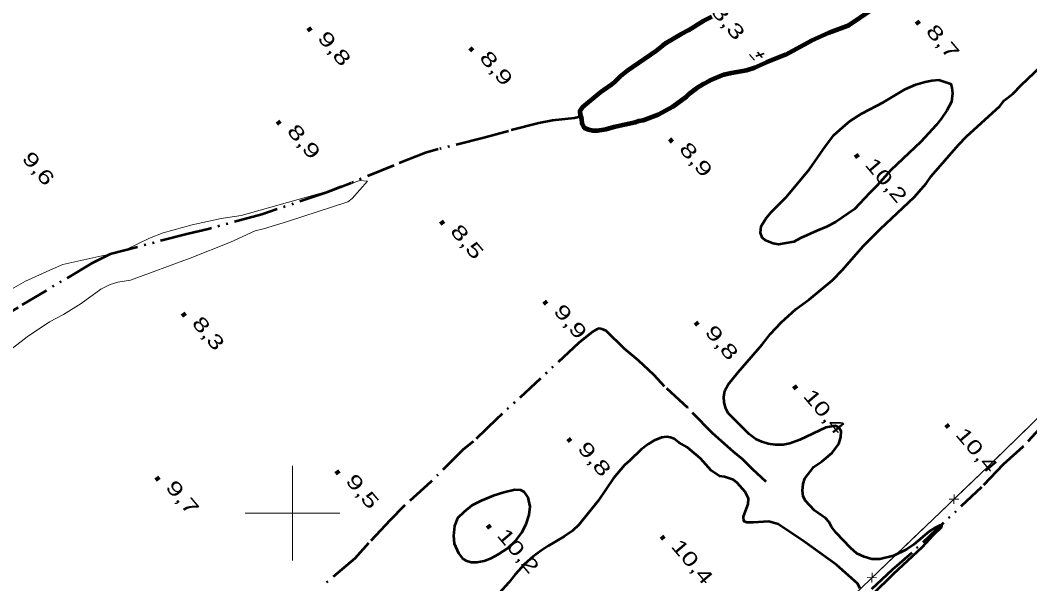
# Model space of a CAD drawing. Extents: x 386081 to 389416, y 5130568 to 5134082.
# Drawn here: x 386742.5 to 386955.8, y 5132585.1 to 5132704.2 of the extents above; entities that cross this region are included whole.
import ezdxf
from ezdxf.enums import TextEntityAlignment as Align

# ---------------------------------------------------------------- set-up
doc = ezdxf.new("R2010")
doc.units = 0
doc.header["$LTSCALE"] = 1.2
doc.linetypes.add('DASH_DOUBLE_DOT', pattern=[9.2, 5, -1.2, 0.3, -1.2, 0.3, -1.2])
for name, color, linetype, lineweight in [('1', 7, 'Continuous', 53), ('2', 7, 'Continuous', 13), ('3', 7, 'Continuous', 140), ('37', 7, 'Continuous', 13), ('4', 7, 'DASH_DOUBLE_DOT', 53), ('61', 7, 'Continuous', 13)]:
    doc.layers.add(name, color=color, linetype=linetype, lineweight=lineweight)

msp = doc.modelspace()

# ---------------------------------------------------------------- linework, layer by layer
at = {"layer": '1'}
for points in [[(386922.59, 5132582.88), (386926.95, 5132587.19), (386933.05, 5132592.85), (386935.42, 5132595.43), (386937.11, 5132597.09), (386937.17, 5132597.4), (386936.8, 5132597.4), (386935.62, 5132596.85), (386934.5, 5132596.11), (386931.26, 5132593.41), (386929.7, 5132592.36), (386926.97, 5132591.02), (386924.11, 5132590.29), (386922.38, 5132590.29), (386920.77, 5132590.79), (386919.22, 5132591.48), (386917.92, 5132592.66), (386914.84, 5132595.88), (386913.86, 5132597.12), (386913.36, 5132598.11), (386912.63, 5132598.98), (386910.28, 5132600.6), (386908.3, 5132602.7), (386907.88, 5132603.63), (386907.76, 5132604.75), (386907.89, 5132606.23), (386908.27, 5132607.34), (386910.14, 5132609.8), (386911.82, 5132610.97), (386914, 5132612.75), (386915.43, 5132614.66), (386915.87, 5132616.08), (386915.94, 5132617.38), (386915.45, 5132618.12), (386914.71, 5132618.5), (386912.72, 5132618.13), (386907.19, 5132615.5), (386905.08, 5132614.76), (386903.65, 5132614.46), (386902.04, 5132614.47), (386900.49, 5132614.66), (386899.19, 5132615.1), (386897.9, 5132615.66), (386896.48, 5132616.71), (386892.04, 5132621.18), (386891.55, 5132622.17), (386891.18, 5132623.4), (386891.12, 5132624.58), (386891.38, 5132625.94), (386892.07, 5132627.23), (386894.19, 5132629.82), (386899.24, 5132635.67), (386901.02, 5132637.95), (386903.23, 5132640.33), (386906.38, 5132643.16), (386909.16, 5132645.22), (386914.11, 5132649.28), (386916.17, 5132651.4), (386920.67, 5132656.51), (386924.26, 5132660.13), (386931.33, 5132666.82), (386933.86, 5132669.69), (386934.92, 5132671.24), (386940.68, 5132677.86), (386942.37, 5132679.65), (386949.47, 5132686.05), (386950.37, 5132687.23), (386952.26, 5132688.71), (386953.96, 5132690.51), (386958.2, 5132694.51)], [(386919.93, 5132584.06), (386919.37, 5132585.12), (386914.93, 5132589.09), (386907.89, 5132594.18), (386902.64, 5132597.72), (386900.66, 5132598.22), (386897.37, 5132598.05), (386896.01, 5132598.06), (386895.39, 5132598.31), (386895.27, 5132599.3), (386896.28, 5132601.89), (386896.32, 5132603.13), (386895.61, 5132604.5), (386893.93, 5132606.41), (386893.2, 5132607.04), (386891.29, 5132607.73), (386890.22, 5132607.86), (386888.43, 5132609.05), (386886.23, 5132611.55), (386883.95, 5132613.45), (386883.42, 5132614), (386881.66, 5132614.98), (386880.67, 5132615.72), (386879.87, 5132616.03), (386879.12, 5132616.16), (386877.94, 5132615.98), (386876.45, 5132615.37), (386875.15, 5132614.57), (386873.66, 5132613.46), (386871.29, 5132611.12), (386870.17, 5132610.14), (386867.8, 5132607.43), (386864.56, 5132602.63), (386860.51, 5132597.52), (386859.14, 5132596.29), (386857.4, 5132595.06), (386853.98, 5132593.04), (386852.49, 5132592.05), (386850.88, 5132590.83), (386849.01, 5132589.23), (386847.08, 5132587.07), (386845.71, 5132585.35), (386843.66, 5132583.08)]]:
    msp.add_lwpolyline(points, dxfattribs=at)
for points in [[(386932.75, 5132678.5), (386926.45, 5132672.53), (386923.46, 5132669.2), (386921.9, 5132667.66), (386918.72, 5132664.27), (386914.74, 5132661.57), (386912.81, 5132660.52), (386910.76, 5132659.73), (386907.35, 5132658.19), (386905.92, 5132657.39), (386902.69, 5132656.79), (386901.57, 5132657.04), (386899.97, 5132657.66), (386899.23, 5132658.28), (386898.86, 5132659.27), (386899.05, 5132660.69), (386900.11, 5132662.36), (386901.17, 5132663.65), (386904.29, 5132666.86), (386909.22, 5132672.71), (386912.59, 5132677.64), (386914.4, 5132679.92), (386916.33, 5132681.71), (386917.76, 5132682.88), (386920.31, 5132684.54), (386924.85, 5132686.94), (386929.46, 5132689.64), (386931.69, 5132690.62), (386933.68, 5132691.24), (386935.05, 5132691.48), (386936.54, 5132691.6), (386939.08, 5132690.79), (386939.32, 5132689.92), (386939.44, 5132688.81), (386939.24, 5132687.01), (386938.24, 5132685.16), (386937.05, 5132683.37), (386935.99, 5132682.08)], [(386846.98, 5132604.92), (386844.69, 5132604.37), (386842.39, 5132603.7), (386839.91, 5132602.6), (386837.93, 5132601.62), (386836.25, 5132600.33), (386834.88, 5132598.98), (386834.25, 5132597.37), (386834.06, 5132595.21), (386834.17, 5132593.61), (386835.09, 5132591.57), (386835.95, 5132590.45), (386836.63, 5132590.02), (386837.74, 5132589.64), (386838.98, 5132589.64), (386840.53, 5132589.94), (386841.96, 5132590.49), (386843.57, 5132591.35), (386845.5, 5132592.64), (386847.3, 5132594.3), (386848.49, 5132595.96), (386849.36, 5132597.69), (386849.99, 5132599.66), (386850.25, 5132601.39), (386849.82, 5132603.3), (386849.02, 5132604.48), (386848.28, 5132604.85)]]:
    msp.add_lwpolyline(points, close=True, dxfattribs=at)
at = {"layer": '2'}
msp.add_lwpolyline([(386736.7, 5132631.73), (386743.99, 5132637.32), (386748.7, 5132640.47), (386751.64, 5132642.01), (386755.35, 5132644.37), (386759.52, 5132647.37), (386761.47, 5132648.37), (386763.11, 5132648.84), (386765.77, 5132649.3), (386778.38, 5132653.91), (386786.95, 5132657.32), (386792.15, 5132659.74), (386793.91, 5132660.15), (386798.98, 5132661.66), (386811.74, 5132665.83), (386812.64, 5132666.55), (386815.88, 5132670.24), (386814.21, 5132670.33), (386812.38, 5132669.73), (386809.96, 5132669.16), (386806.97, 5132667.98), (386789.17, 5132662.94), (386784.95, 5132662.28), (386778.81, 5132660.95), (386772.68, 5132659.28), (386769.84, 5132658.13), (386765.14, 5132655.9), (386762.15, 5132654.83), (386759.76, 5132654.4), (386751.51, 5132652.57), (386749.36, 5132651.7), (386743.6, 5132649.04), (386740.68, 5132647.34)], dxfattribs=at)
at = {"layer": '3'}
for p, q in [((386931.82, 5132704.03), (386932.33, 5132703.42)), ((386803.3, 5132702.6), (386803.81, 5132701.99)), ((386837.51, 5132698.43), (386838.02, 5132697.82)), ((386796.86, 5132682.92), (386797.37, 5132682.31)), ((386879.69, 5132679.13), (386880.2, 5132678.52)), ((386918.95, 5132675.85), (386919.46, 5132675.24)), ((386831.35, 5132661.75), (386831.86, 5132661.14)), ((386853.16, 5132644.87), (386853.67, 5132644.26)), ((386776.77, 5132642.29), (386777.28, 5132641.68)), ((386885.13, 5132640.43), (386885.64, 5132639.82)), ((386905.9, 5132626.93), (386906.41, 5132626.32)), ((386938.09, 5132618.78), (386938.6, 5132618.17)), ((386858.24, 5132615.82), (386858.75, 5132615.21)), ((386771.2, 5132607.63), (386771.71, 5132607.02)), ((386809.24, 5132608.97), (386809.75, 5132608.36)), ((386841.21, 5132597.48), (386841.72, 5132596.87)), ((386877.98, 5132595.18), (386878.49, 5132594.57))]:
    msp.add_line(p, q, dxfattribs=at)
at = {"layer": '3', "lineweight": 35}
for p, q in [((386896.59, 5132697.01), (386897.63, 5132695.79)), ((386899.69, 5132697.22), (386897.87, 5132696.65)), ((386898.26, 5132697.51), (386899.27, 5132696.32))]:
    msp.add_line(p, q, dxfattribs=at)
at = {"layer": '37'}
for p, q in [((386948.42, 5132611.28), (386955.56, 5132618.28)), ((386940.76, 5132602.94), (386938.76, 5132602.99)), ((386939.74, 5132601.96), (386939.78, 5132603.97)), ((386931.09, 5132594.67), (386938.32, 5132601.58)), ((386923.87, 5132587.76), (386931.09, 5132594.67)), ((386923.42, 5132586.35), (386921.42, 5132586.4)), ((386922.4, 5132585.37), (386922.44, 5132587.37))]:
    msp.add_line(p, q, dxfattribs=at)
for points in [[(386878.76, 5132545.22), (386893.86, 5132559.29), (386912.04, 5132576.44), (386947.01, 5132609.9), (386966.08, 5132628.58), (386986.5, 5132647.98), (387002.12, 5132661.95), (387004.89, 5132659.44), (387006.04, 5132660.44), (387041.04, 5132693.88), (387075.38, 5132725.65), (387084.05, 5132734.26)], [(386941.21, 5132604.35), (386947.01, 5132609.9), (386948.42, 5132611.28)]]:
    msp.add_lwpolyline(points, dxfattribs=at)
at = {"layer": '4', "linetype": 'Continuous', "lineweight": 90}
msp.add_lwpolyline([(386888.57, 5132704.93), (386886.77, 5132704.01), (386883.78, 5132702.16), (386882.16, 5132701.3), (386879.05, 5132699.45), (386878.24, 5132698.9), (386876.74, 5132697.67), (386870.7, 5132693.54), (386869.33, 5132692.43), (386868.09, 5132691.2), (386867.34, 5132690.58), (386865.04, 5132688.92), (386861.3, 5132685.84), (386860.74, 5132685.03), (386860.79, 5132684.23), (386861.04, 5132683.36), (386861.16, 5132682.37), (386861.65, 5132681.5), (386862.52, 5132681.13), (386863.45, 5132680.94), (386864.44, 5132680.94), (386866.18, 5132681.18), (386867.92, 5132681.67), (386872.39, 5132682.65), (386873.2, 5132682.95), (386874.07, 5132683.07), (386877.3, 5132684.3), (386880.35, 5132685.96), (386883.27, 5132688.12), (386883.9, 5132688.73), (386885.39, 5132689.84), (386886.82, 5132690.77), (386888.19, 5132691.51), (386891.18, 5132692.73), (386892.79, 5132693.1), (386895.96, 5132693.65), (386897.7, 5132694.26), (386900.19, 5132695.37), (386904.24, 5132697.02), (386909.65, 5132699.92), (386913.39, 5132701.64), (386917.55, 5132703.17), (386922.35, 5132706.44)], dxfattribs=at)
at = {"layer": '4'}
for points in [[(386860.9, 5132683.86), (386859.61, 5132683.55), (386854.96, 5132683.01), (386852.04, 5132682.46), (386845.64, 5132680.81), (386840.43, 5132679.35), (386830.8, 5132676.97), (386828.14, 5132676.17), (386821.41, 5132673.54), (386812.4, 5132669.8), (386807.25, 5132667.78), (386793.53, 5132663.19), (386782.18, 5132660.07), (386777.96, 5132659.1), (386761.52, 5132654.76), (386757.55, 5132652.8), (386742.09, 5132643.52), (386734.61, 5132639.17), (386731.51, 5132637.57), (386730.21, 5132637.02)], [(386900.11, 5132606.63), (386897.21, 5132609.3), (386895.11, 5132611.41), (386893.2, 5132612.96), (386888.76, 5132616.93), (386883.51, 5132622.27), (386878.63, 5132626.8), (386876.41, 5132629.16), (386873.13, 5132632.26), (386870.17, 5132634.75), (386866.28, 5132638.53), (386865.42, 5132638.91), (386864.8, 5132639.03), (386864.24, 5132638.85), (386863.37, 5132638.36), (386860.51, 5132636.02), (386843.13, 5132619.89), (386838.21, 5132615.15), (386836.03, 5132613.37), (386829.24, 5132606.66), (386823.58, 5132601.55), (386820.65, 5132598.54), (386816.11, 5132593.68), (386813.18, 5132590.41), (386806.51, 5132584.75)], [(386959.43, 5132619.62), (386954.32, 5132614.02), (386950.14, 5132610.27), (386945.59, 5132605.52), (386930.82, 5132591.62), (386926.71, 5132588.05), (386918.68, 5132580.48)]]:
    msp.add_lwpolyline(points, dxfattribs=at)
at = {"layer": '61'}
for p, q in [((386800, 5132590), (386800, 5132610)), ((386790, 5132600), (386810, 5132600))]:
    msp.add_line(p, q, dxfattribs=at)

# ---------------------------------------------------------------- texts
at = {"layer": '3', "width": 1.5}
msp.add_text('    8,3', height=3, rotation=310.294, dxfattribs=at).set_placement((386888.735, 5132705.465), align=Align.CENTER)
at = {"layer": '3'}
for s, width, p in [('8,7    ', 1.45, (386933.65, 5132701.81)), ('9,8    ', 1.45, (386805.13, 5132700.38)), ('8,9    ', 1.45, (386839.34, 5132696.21)), ('8,9    ', 1.45, (386798.69, 5132680.7)), ('8,9    ', 1.45, (386881.52, 5132676.91)), ('9,6    ', 1.4, (386742.7, 5132674.91)), ('10,2   ', 1.4, (386920.78, 5132673.63)), ('8,5    ', 1.45, (386833.18, 5132659.53)), ('9,9    ', 1.45, (386854.99, 5132642.65)), ('8,3    ', 1.4, (386778.6, 5132640.07)), ('9,8    ', 1.45, (386886.96, 5132638.21)), ('10,4   ', 1.4, (386907.73, 5132624.71)), ('10,4   ', 1.4, (386939.92, 5132616.56)), ('9,8    ', 1.45, (386860.07, 5132613.6)), ('9,5    ', 1.45, (386811.07, 5132606.75)), ('9,7    ', 1.45, (386773.03, 5132605.41)), ('10,2   ', 1.4, (386843.04, 5132595.26)), ('10,4   ', 1.4, (386879.81, 5132592.96))]:
    msp.add_text(s, height=3, rotation=310.294, dxfattribs=dict(at, width=width)).set_placement(p)

doc.saveas('drawing.dxf')
